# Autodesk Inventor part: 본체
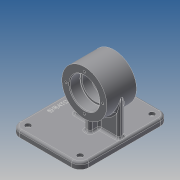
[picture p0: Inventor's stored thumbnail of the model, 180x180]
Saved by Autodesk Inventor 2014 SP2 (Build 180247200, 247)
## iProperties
Created: 2019-09
Part Number: 본체
Material: Generic
Document SubType Name: Modeling
Designer: kb542-10
Density: 1 g/cm^3
Appearance: Default
Author: kb542-10
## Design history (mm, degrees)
sketch "스케치1"
  geometry: C1 r 32 at (0, 0); 1 further point
  constraints: 1 centre point, 1 coincident
  dimensions: "d0" = 64 diameter of C1
extrude "돌출1" new body sketch "스케치1" stored distance "d1" = 42; taper "d2" = 0 deg
sketch "스케치2"
  geometry: C1 r 32 at (0, 0) reference; C2 r 21 at (0, 0)
  constraints: 1 centre point, 1 coincident
  dimensions: "d3" = 42 diameter of C2
extrude "돌출2" cut sketch "스케치2" distance "d4" = 15; taper "d5" = 0 deg
sketch "스케치3"
  geometry: C1 r 32 at (0, 0) reference; C2 r 21 at (0, 0)
  constraints: 1 centre point, 1 coincident
  dimensions: "d6" = 42 diameter of C2
extrude "돌출3" cut sketch "스케치3" distance "d7" = 15; taper "d8" = 0 deg
sketch "스케치4"
  geometry: C1 r 21 at (0, 0) reference; C2 r 18 at (0, 0)
  constraints: 1 centre point, 1 coincident
  dimensions: "d9" = 36 diameter of C2
extrude "돌출4" cut sketch "스케치4" stored distance "d10" = 15; taper "d11" = 0 deg
sketch "스케치7"
  geometry: L1 (-63, -50)-(63, -50); L2 (63, -50)-(63, -59); L3 (63, -59)-(-63, -59); L4 (-63, -59)-(-63, -50); L5 (-21, -32)-(21, -32) reference; 2 further points
  constraints: 8 end point, 2 parallel, 1 horizontal, 1 midpoint, 1 perpendicular, 1 vertical alignment
  dimensions: "d15" = 59 distance from line of L3 point (0, 0); "d16" = 9 distance of L1.end L2.end; "d17" = 126 distance of L1.start L1.end
extrude "돌출5" join sketch "스케치7" distance "d18" = 36; taper "d20" = 0 deg; dims "d19" = 62, "d21" = 0
sketch "스케치8"
  geometry: L1 (-36, -50)-(62, -50) reference; L2 (-36, -59)-(-36, -50) reference; L3 (-36, -59)-(62, -59) reference; L4 (62, -50)-(62, -59) reference; L5 (32, 0)-(32, -50); L6 (-32, 0)-(-32, -50); A1 r 32 centre (0, 0) between (32, 0) and (-32, 0) reference; 1 further point
  constraints: 4 end point, 2 perpendicular, 2 point on circle, 2 point on line, 2 tangent
extrude "돌출6" join sketch "스케치8" stored distance "d22" = 8; taper "d23" = 0 deg
sketch "스케치9"
  geometry: L1 (-21, -32)-(21, -32) reference; L2 (63, -50)-(-63, -50) reference; L3 (-17, -32)-(-17, -50); L4 (17, -32)-(17, -50); 1 further point
  constraints: 4 end point, 4 point on line, 2 perpendicular
  dimensions: "d24" = 17 distance from line of L4 point (0, 0); "d25" = 17 distance from line of L3 point (0, 0)
feature "리브1" dims "d53" = 1, "d54" = 8, "d55" = 0, "d56" = 0, "d57" = 1, "d58" = 1
feature "리브2" dims "d59" = 1, "d60" = 8, "d61" = 0, "d62" = 0, "d63" = 1, "d64" = 1
sketch "스케치10"
  geometry: C1 r 21 at (0, 0) reference; 1 further point
  constraints: 1 vertical alignment
  dimensions: "d28" = 26 distance of C1.centre point (0, 26)
hole "구멍1" sketch "스케치10" at (0, 26) diameter "d29" = 3.242; stored, may be unused: countersink angle "d33" = 90 deg, drill point angle "d35" = 118 deg; dims "d30" = 8, "d31" = 4, "d32" = 2, "d34" = 10
fillet "모깎기1" dims "d39" = 12
sketch "스케치11"
  geometry: A1 r 12 centre (74, -12) between (86, -12) and (74, 0) reference; A2 r 12 centre (0, -12) between (0, 0) and (-12, -12) reference; A3 r 12 centre (0, -114) between (-12, -114) and (0, -126) reference; A4 r 12 centre (74, -114) between (74, -126) and (86, -114) reference; 5 further points
  constraints: 4 coincident
hole "구멍2" sketch "스케치11" at (0, -12), (0, -114), (74, -114), (74, -12) diameter "d40" = 4.5; stored, may be unused: countersink angle "d44" = 90 deg, drill point angle "d46" = 118 deg; dims "d41" = 4.5, "d42" = 8, "d43" = 4.4, "d45" = 10
fillet "모깎기2" dims "d51" = 3
fillet "모깎기4" dims "d65" = 3
fillet "모깎기5" dims "d66" = 3
fillet "모깎기6" dims "d67" = 3
fillet "모깎기7" dims "d68" = 0.3
chamfer "모따기1" distance "d69" = 1; stored, may be unused: second distance "d70" = 2, angle "d71" = 45 deg
sketch "스케치13"
  geometry: L1 (74, 3)-(0, 3) reference; L2 (-12, -9)-(-12, -111) reference; 2 further points
  constraints: 1 other
  dimensions: "d72" = 63 distance from line of point (-2, -60) L1; "d73" = 10 distance from line of point (-2, -60) L2
feature "엠보싱2" sketch "스케치13" dims "d1" = 42, "d2" = 0, "d74" = 0.5, "d75" = 0
node "솔리드1"
pattern_circular "원형 패턴1" dims angle "d37" = 360 deg
mirror "대칭1"
node "투영된 루프1"
